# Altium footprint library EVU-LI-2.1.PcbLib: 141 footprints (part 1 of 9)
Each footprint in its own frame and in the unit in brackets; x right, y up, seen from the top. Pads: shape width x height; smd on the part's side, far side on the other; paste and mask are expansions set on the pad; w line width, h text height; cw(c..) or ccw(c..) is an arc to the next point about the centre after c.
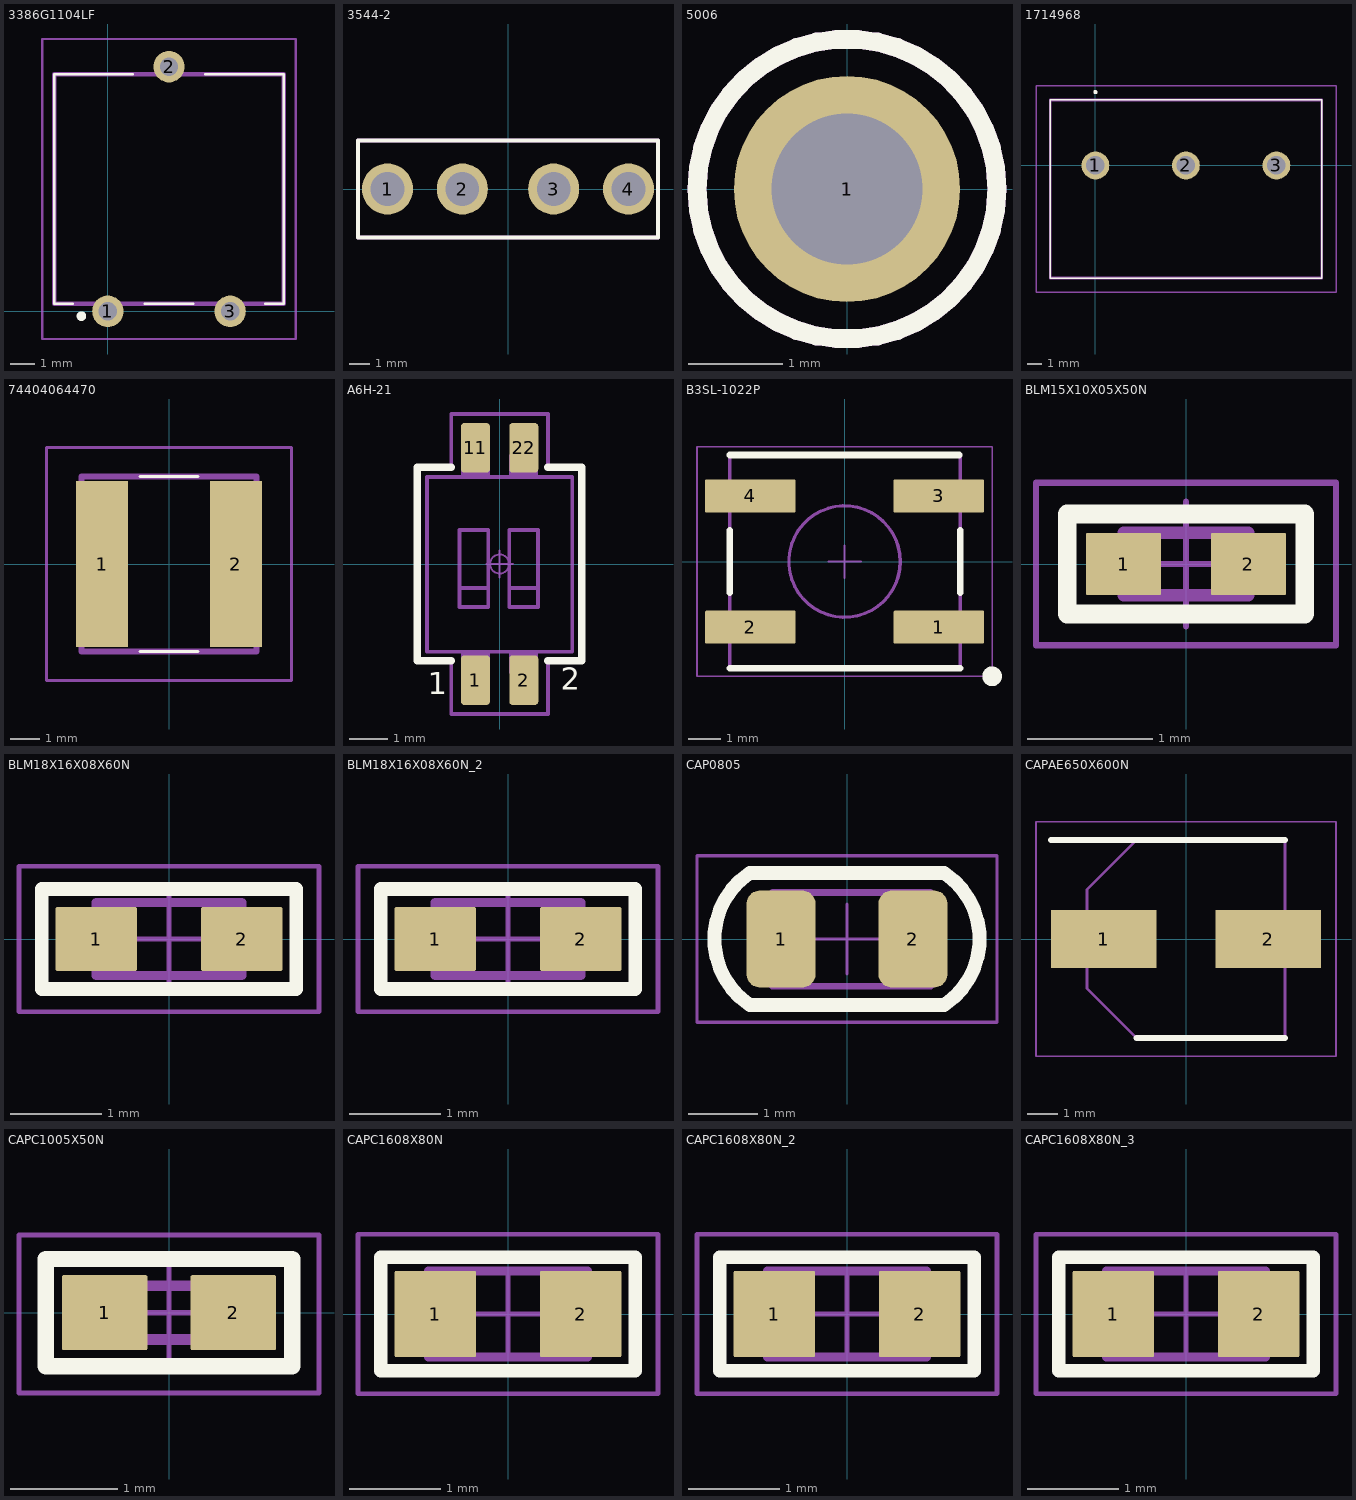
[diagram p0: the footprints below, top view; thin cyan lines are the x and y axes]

## 3386G1104LF [mm]
pads (3):
  round 1.303 hole 0.76: 1(0,0) 2(2.54,10.16) 3(5.08,0)
Top Overlay:
  lines w0.1: -1.46,0.315 -2.225,0.315 -2.225,9.845 1.04,9.845 ; 1.54,0.315 3.54,0.315 ; 4.04,9.845 7.305,9.845 7.305,0.315 6.54,0.315
  lines w0.2: -1.1,-0.3 ccw(c-1.1,-0.2) -1.1,-0.1 ccw(c-1.1,-0.2) -1.1,-0.3
Mechanical 13:
  lines w0.2: -2.225,0.315 -2.225,9.845 7.305,9.845 7.305,0.315 -2.225,0.315
Top Courtyard:
  lines w0.1: -2.725,-1.151 -2.725,11.311 7.805,11.311 7.805,-1.151 -2.725,-1.151
3D body "3386G-1-104LF.stp": height 4.93, standoff -5, extent -2.225,-0.278 7.305,10.438

## 3544-2 [mm]
pads (4):
  round 2.5 hole 1.65: 1(-5.895,0) 2(-2.235,0) 3(2.235,0) 4(5.895,0)
Top Overlay:
  lines w0.2: -7.34,-2.375 7.34,-2.375 7.34,2.375 -7.34,2.375 -7.34,-2.375
Mechanical 13:
  lines w0.2: -7.34,-2.375 -7.34,2.375 7.34,2.375 7.34,-2.375 -7.34,-2.375
3D body "3544-2.stp": height 1.85, standoff -2.9, extent -5.444,-4.755 9.237,6.421

## 5006 [mm]
pads (1):
  round 2.4 hole 1.6: 1(0,0)
Top Overlay:
  circle w0.2: c0,0 r1.59
Assembly Notes:
  circle w0.2: c0,0 r1.59
3D body "5005.stp": height 5.6, standoff -3.28, extent -1.587,-1.576 1.587,1.576

## 1714968 [mm]
pads (3):
  round 1.95 hole 1.3: 1(0,0) 2(6.35,0) 3(12.7,0)
Top Overlay:
  lines w0.1: -3.17,-7.9 -3.17,4.6 15.88,4.6 15.88,-7.9 -3.17,-7.9
  lines w0.2: 0,5.1 ccw(c0,5.15) 0,5.2 ; 0,5.1 cw(c0,5.15) 0,5.2 ; 0,5.1 ccw(c0,5.15) 0,5.2
Mechanical 13:
  lines w0.2: -3.17,-7.9 -3.17,4.6 15.88,4.6 15.88,-7.9 -3.17,-7.9
Top Courtyard:
  lines w0.1: -4.17,-8.9 -4.17,5.6 16.88,5.6 16.88,-8.9 -4.17,-8.9
3D body "1714968.stp": height 22.04, standoff -4.46, extent -3.83,-7.9 15.79,4.6

## 74404064470 [mm]
pads (2):
  rect 1.8x5.7 smd: 1(-2.3,0) 2(2.3,0)
Top Overlay:
  lines w0.1: -1,-3 1,-3 ; -1,3 1,3
Mechanical 13:
  lines w0.2: -3,-3 3,-3 3,3 -3,3 -3,-3
Top Courtyard:
  lines w0.1: -4.2,-4 4.2,-4 4.2,4 -4.2,4 -4.2,-4
3D body "74404064100.stp": height 4.1, standoff 0, extent -3.02,-3 3.02,3

## A6H-21 [mm] "SWITCH SMT 2-WAY"
height 2.3
pads (4):
  rrect22% 0.76x1.3 smd: 1(-0.635,-3.048) 2(0.635,-3.048) 11(-0.635,3.048) 22(0.635,3.048)
Top Overlay:
  lines w0.2: -1.27,-2.54 -2.159,-2.54 -2.159,2.54 -1.27,2.54 ; 1.27,-2.54 2.159,-2.54 2.159,2.54 1.27,2.54
  text "1" at -1.885,-3.614 h1
  text "2" at 1.6,-3.502 h1
Top Assembly:
  rectangle: -0.889,-3.502 -0.381,-2.302
  region: -0.254,-2.885 -0.254,-2.302 -1.016,-2.302 -1.016,-2.885
  rectangle: 0.373,-3.486 0.881,-2.286
  region: 1.008,-2.869 1.008,-2.286 0.246,-2.286 0.246,-2.869
  region: 0.883,3.486 0.375,3.486 0.375,2.286 0.883,2.286
  region: 0.248,2.869 0.248,2.286 1.01,2.286 1.01,2.869
  region: -0.379,3.47 -0.887,3.47 -0.887,2.27 -0.379,2.27
  region: -1.014,2.853 -1.014,2.27 -0.252,2.27 -0.252,2.853
  lines w0.1: -1.049,-0.633 -0.299,-0.633 ; 0.254,-0.633 1.004,-0.633 ; -1.905,-2.302 -1.905,2.286 1.905,2.286 1.905,-2.302 -1.905,-2.302 ; -1.049,-1.129 -1.049,0.889 -0.299,0.889 -0.299,-1.129 -1.049,-1.129 ; 0.254,-1.129 0.254,0.889 1.004,0.889 1.004,-1.129 0.254,-1.129
  text "1" at -0.889,-2.032 h1
  text "2" at 0.381,-2.032 h1
  text ".Designator" at -3.367,1.139 h2
Top Value:
  text ".comment" at -1.651,-0.762 h1
Top Courtyard:
  circle w0.05: c0,0 r0.25
  lines w0.05: -0.35,0 0.35,0 ; 0,-0.35 0,0.35
  lines w0.1: -2.159,-2.552 -2.159,2.54 -1.27,2.54 -1.27,3.937 1.27,3.937 1.27,2.54 2.159,2.54 2.159,-2.552 1.27,-2.552 1.27,-3.937 -1.27,-3.937 -1.27,-2.552 -2.159,-2.552
3D body "User Library-A6H-21.STEP": height 1.55, standoff 0, extent -1.885,-3.35 1.885,3.35

## B3SL-1022P [mm]
pads (4):
  rrect5% 2.75x1 smd mask+0.07: 1(2.875,-2) 2(-2.875,-2) 3(2.875,2) 4(-2.875,2)
Top Overlay:
  circle w0.3: c4.5,-3.5 r0.15
  lines w0.2: -3.5,-3.25 3.525,-3.25 ; -3.5,-0.95 -3.5,0.95 ; -3.5,3.25 3.5,3.25 ; 3.525,-0.95 3.525,0.95
Top Assembly:
  circle w0.1: c0,0 r1.7
  lines w0.1: -3.5,-3.25 3.525,-3.25 3.525,3.25 -3.5,3.25 -3.5,-3.25
Top Designator:
  text ".Designator" at 1.026,-3.683 h1.5
Top Courtyard:
  lines w0.05: -0.5,0 0.5,0 ; 0,-0.5 0,0.5 ; -4.5,-3.5 4.5,-3.5 4.5,3.5 -4.5,3.5 -4.5,-3.5
3D body "B3SL-1022P.STEP": height 5.1, standoff 0, extent -3.5,-3.25 3.5,3.25

## BLM15X10X05X50N [mm]
height 0.5
pads (2):
  rrect5% 0.6x0.5 smd mask+0.07: 1(-0.5,0) 2(0.5,0)
Top Overlay:
  lines w0.15: -0.95,-0.4 -0.95,0.4 0.95,0.4 0.95,-0.4 -0.95,-0.4
Top Assembly:
  lines w0.1: -0.5,-0.25 -0.5,0.25 0.5,0.25 0.5,-0.25 -0.5,-0.25
Top Designator:
  text ".Designator" at -3.25,-0.3 h1.5
Top Courtyard:
  lines w0.05: -0.5,0 0.5,0 ; 0,-0.5 0,0.5 ; -1.2,-0.65 -1.2,0.65 1.2,0.65 1.2,-0.65 -1.2,-0.65
3D body "BLM15.STEP": height 0.5, standoff 0, extent -0.5,-0.25 0.5,0.25

## BLM18X16X08X60N [mm]
pads (2):
  rrect5% 0.9x0.7 smd mask+0.07: 1(-0.8,0) 2(0.8,0)
Top Overlay:
  lines w0.15: -1.4,-0.55 1.4,-0.55 1.4,0.55 -1.4,0.55 -1.4,-0.55
Top Assembly:
  lines w0.1: -0.8,-0.4 -0.8,0.4 0.8,0.4 0.8,-0.4 -0.8,-0.4
Top Designator:
  text ".Designator" at -3.25,-0.3 h1.5
Top Courtyard:
  lines w0.05: -0.5,0 0.5,0 ; 0,-0.5 0,0.5 ; -1.65,-0.8 -1.65,0.8 1.65,0.8 1.65,-0.8 -1.65,-0.8
3D body "BLM18__SN1.STEP": height 0.95, standoff 0, extent -0.875,-0.475 0.875,0.475

## BLM18X16X08X60N_2 [mm]
pads (2):
  rrect5% 0.9x0.7 smd mask+0.07: 1(-0.8,0) 2(0.8,0)
Top Overlay:
  lines w0.15: -1.4,-0.55 1.4,-0.55 1.4,0.55 -1.4,0.55 -1.4,-0.55
Top Assembly:
  lines w0.1: -0.8,-0.4 -0.8,0.4 0.8,0.4 0.8,-0.4 -0.8,-0.4
Top Designator:
  text ".Designator" at -3.25,-0.3 h1.5
Top Courtyard:
  lines w0.05: -0.5,0 0.5,0 ; 0,-0.5 0,0.5 ; -1.65,-0.8 -1.65,0.8 1.65,0.8 1.65,-0.8 -1.65,-0.8
3D body "BLM18__SN1.STEP": height 0.95, standoff 0, extent -0.875,-0.475 0.875,0.475

## CAP0805 [mm] "SMD Ceramic Chip Capacitor 0805,  metric 2012"
height 1
pads (2):
  rrect40% 1x1.4 smd: 1(-0.95,0) 2(0.95,0)
Top Overlay:
  lines w0.2: -1.4,-0.95 cw(c-0.77,0) -1.4,0.95 1.4,0.95 cw(c0.77,0) 1.4,-0.95 -1.4,-0.95
Top Assembly:
  lines w0.1: -1.07,-0.68 -1.07,0.67 1.2,0.67 1.2,-0.68 -1.07,-0.68
  text ".Designator" at -2.212,-0.231 h1.2
Top Value:
  text ".Comment" at -0.77,-0.25 h0.5
Top Courtyard:
  lines w0.05: -0.5,0 0.5,0 ; 0,-0.5 0,0.5 ; -2.16,-1.2 -2.16,1.2 2.16,1.2 2.16,-1.2 -2.16,-1.2
3D body "SMD_CAPACITOR_0805.step": height 0.6, standoff 0, extent -1,-0.625 1,0.625

## CAPAE650X600N [mm]
pads (2):
  rect 3.45x1.9 smd: 1(-2.7,0) 2(2.7,0)
Top Overlay:
  lines w0.2: -4.425,3.25 3.25,3.25 ; -1.625,-3.25 3.25,-3.25
Mechanical 13:
  lines w0.1: -3.25,-1.625 -3.25,1.625 -1.625,3.25 3.25,3.25 3.25,-3.25 -1.625,-3.25 -3.25,-1.625
Top Courtyard:
  lines w0.05: -4.925,-3.85 4.925,-3.85 4.925,3.85 -4.925,3.85 -4.925,-3.85
3D body "RSS1E470MCN1GS.stp": height 6, standoff 0, extent -3.7,-3.35 3.7,3.35

## CAPC1005X50N [mm]
pads (2):
  rrect5% 0.8x0.7 smd paste-25.4 mask+0.07: 1(-0.6,0) 2(0.6,0)
Top Overlay:
  lines w0.15: -1.15,-0.5 -1.15,0.5 1.15,0.5 1.15,-0.5 -1.15,-0.5
Top Paste:
  region: 0.359,-0.241 0.841,-0.241 0.841,0.241 0.359,0.241
  region: -0.841,-0.241 -0.359,-0.241 -0.359,0.241 -0.841,0.241
Top Assembly:
  lines w0.1: -0.508,-0.25 0.492,-0.25 0.492,0.25 -0.508,0.25 -0.508,-0.25
Top Designator:
  text ".Designator" at -3.25,-0.3 h1.5
Top Courtyard:
  lines w0.05: -0.5,0 0.5,0 ; 0,-0.5 0,0.5 ; -1.4,-0.75 1.4,-0.75 1.4,0.725 -1.4,0.725 -1.4,-0.75
3D body "0402c.STEP": height 0.55, standoff 0, extent -0.575,-0.275 0.575,0.275

## CAPC1608X80N [mm]
pads (2):
  rrect5% 0.9x0.95 smd mask+0.07: 1(-0.8,0) 2(0.8,0)
Top Overlay:
  lines w0.15: -1.4,-0.625 1.4,-0.625 1.4,0.625 -1.4,0.625 -1.4,-0.625
Top Assembly:
  lines w0.1: -0.875,-0.475 0.875,-0.475 0.875,0.475 -0.875,0.475 -0.875,-0.475
Top Designator:
  text ".Designator" at -3.25,-0.3 h1.5
Top Courtyard:
  lines w0.05: -0.5,0 0.5,0 ; 0,-0.5 0,0.5 ; -1.65,-0.875 1.65,-0.875 1.65,0.875 -1.65,0.875 -1.65,-0.875
3D body "0603c.STEP": height 0.85, standoff 0, extent -0.875,-0.475 0.875,0.475

## CAPC1608X80N_2 [mm]
pads (2):
  rrect5% 0.9x0.95 smd mask+0.07: 1(-0.8,0) 2(0.8,0)
Top Overlay:
  lines w0.15: -1.4,-0.625 -1.4,0.625 1.4,0.625 1.4,-0.625 -1.4,-0.625
Top Assembly:
  lines w0.1: -0.875,-0.475 -0.875,0.475 0.875,0.475 0.875,-0.475 -0.875,-0.475
Top Designator:
  text ".Designator" at -3.25,-0.3 h1.5
Top Courtyard:
  lines w0.05: -0.5,0 0.5,0 ; 0,-0.5 0,0.5 ; -1.65,-0.875 -1.65,0.875 1.65,0.875 1.65,-0.875 -1.65,-0.875
3D body "0603c.STEP": height 0.85, standoff 0, extent -0.875,-0.475 0.875,0.475

## CAPC1608X80N_3 [mm]
pads (2):
  rrect5% 0.9x0.95 smd mask+0.07: 1(-0.8,0) 2(0.8,0)
Top Overlay:
  lines w0.15: -1.4,-0.625 1.4,-0.625 1.4,0.625 -1.4,0.625 -1.4,-0.625
Top Assembly:
  lines w0.1: -0.875,-0.475 0.875,-0.475 0.875,0.475 -0.875,0.475 -0.875,-0.475
Top Designator:
  text ".Designator" at -3.25,-0.3 h1.5
Top Courtyard:
  lines w0.05: -0.5,0 0.5,0 ; 0,-0.5 0,0.5 ; -1.65,-0.875 1.65,-0.875 1.65,0.875 -1.65,0.875 -1.65,-0.875
3D body "0603c.STEP": height 0.85, standoff 0, extent -0.875,-0.475 0.875,0.475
